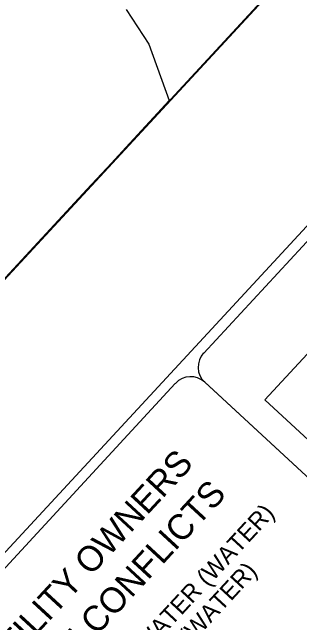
# Model space of a CAD drawing. Extents: x 1766669 to 1770980, y 998119 to 1002502.
# Drawn here: x 1769269 to 1769573, y 999625 to 1000271 of the extents above; entities that cross this region are included whole.
import ezdxf

# ---------------------------------------------------------------- set-up
doc = ezdxf.new("R2010")
doc.units = 0
for name, color, linetype in [('Default Symbol CELL', 7, 'Continuous'), ('Exist Hydro Stream or Body of Water', 7, 'Continuous'), ('Exist Survey Setup Group', 7, 'Continuous'), ('PH Exist DTM Point', 7, 'Continuous')]:
    doc.layers.add(name, color=color, linetype=linetype)

msp = doc.modelspace()

# ---------------------------------------------------------------- linework, layer by layer
at = {"layer": 'Default Symbol CELL'}
for p, q in [((1768227.41, 998581.09), (1770560.11, 1001104.69)), ((1769471.08, 999910.15), (1769858.81, 1000329.61)), ((1769164.92, 999579.1), (1769441.1, 999878.05)), ((1769730.42, 999640.53), (1769472.24, 999879.18))]:
    msp.add_line(p, q, dxfattribs=at)
msp.add_lwpolyline([(1769607.3, 999937.94), (1769535.79, 999860.66), (1769600.23, 999801.02), (1769671.75, 999878.31), (1769607.3, 999937.94)], dxfattribs=at)
msp.add_lwpolyline([(1769607.3, 999937.94), (1769535.79, 999860.66), (1769600.23, 999801.02), (1769671.75, 999878.31), (1769607.3, 999937.94)], dxfattribs=at)
for centre, start, end in [((1769487.15, 999895.31), 137.25123, 227.25123), ((1769457.24, 999863.14), 47.25123, 137.25123)]:
    msp.add_arc(centre, 21.97, start, end, dxfattribs=at)
at = {"layer": 'Exist Hydro Stream or Body of Water'}
msp.add_lwpolyline([(1769389.29, 1000273.68), (1769413.2, 1000236.82), (1769434.54, 1000177.13), (1769413.64, 1000154.52), (1769388.7, 1000127.54), (1769373.48, 1000111.07), (1769347.57, 1000083.05), (1769313.19, 1000045.85), (1769261.49, 999989.92), (1769234.38, 999960.6), (1768951.55, 999915.73), (1768913.01, 999840.27), (1768850.95, 999744.91), (1768806.91, 999689.94), (1768769.64, 999629), (1768740.15, 999567.01), (1768697.93, 999504.02), (1768671.87, 999439.68), (1768638.15, 999315.57)], dxfattribs=at)
at = {"layer": 'Exist Survey Setup Group'}
for points in [[(1768011.06, 999850.81), (1769408.21, 1001362.3), (1770013.17, 1000803.11), (1768616.02, 999291.62)], [(1768011.06, 999850.81), (1769409.41, 1001362.02), (1770014.25, 1000802.35), (1768615.91, 999291.14)]]:
    msp.add_lwpolyline(points, close=True, dxfattribs=at)
at = {"layer": 'PH Exist DTM Point'}
msp.add_line((1769471.87, 999879.52), (1769610.65, 999751.23), dxfattribs=at)

# ---------------------------------------------------------------- texts
at = {"layer": 'Default Symbol CELL'}
for s, height, p in [('UTILITY OWNERS', 26.8484, (1769254.15, 999568.19)), ('WITH CONFLICTS', 26.8484, (1769288.99, 999535.96)), ('(A) DAN RIVER WATER (WATER)', 18.4712, (1769287.12, 999458.71)), ('(B) CITY OF EDEN (WATER)', 18.4712, (1769307.88, 999439.52))]:
    msp.add_text(s, height=height, rotation=47.237, dxfattribs=at).set_placement(p)

doc.saveas('drawing.dxf')
